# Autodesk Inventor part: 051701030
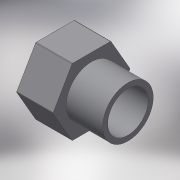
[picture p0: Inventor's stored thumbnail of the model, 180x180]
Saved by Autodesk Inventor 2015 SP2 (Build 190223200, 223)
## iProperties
Created: 2017-10
Part Number: 051701030
Material: Generic
Description: PLASSON THREADED PLUG PVC 3"
Document SubType Name: Modeling
Designer: KIM
Density: 1 g/cm^3
Appearance: Default
Author: KIM
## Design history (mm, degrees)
derived "051701.ipt"
feature "Solid1::051701.ipt"
tag "TaggingFeature1"
body "Solid1"
other parameters: "d0" = 61, "d1" = 87.884, "d2" = 1, "d4" = 95, "d6" = 70.3072, "d10" = 0, "d18" = 0.95, "d19" = 33, "d20" = 42.7, "R_" = 87.884, "C_" = 95, "Lt_" = 33, "H_" = 61
